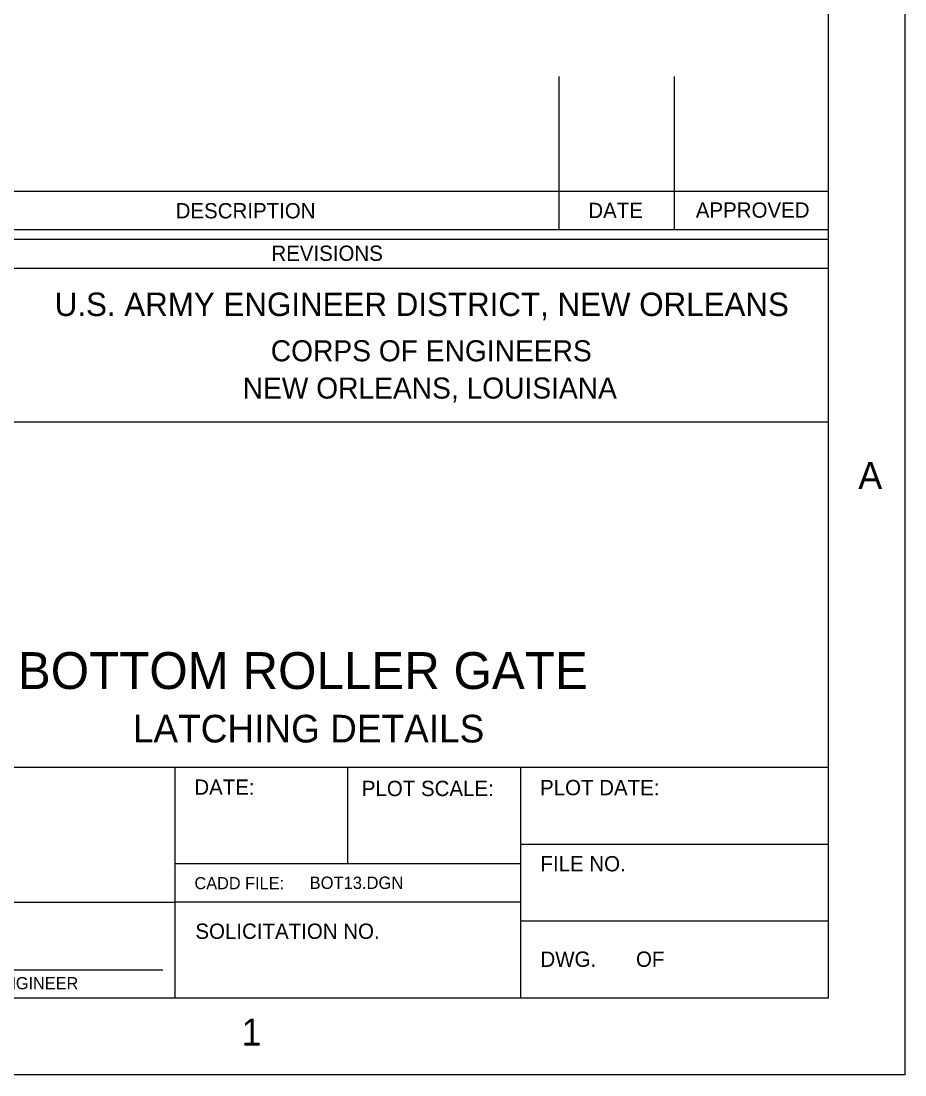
# Model space of a CAD drawing. Extents: x 0 to 320, y -4 to 473.
# Drawn here: x 308.95 to 320.45, y 417.42 to 431.14 of the extents above; entities that cross this region are included whole.
import ezdxf

# ---------------------------------------------------------------- set-up
doc = ezdxf.new("R2010")
doc.units = 0
doc.layers.add('Level 1', color=7, linetype='Continuous')
doc.layers.add('Level 2', color=7, linetype='Continuous')

msp = doc.modelspace()

# ---------------------------------------------------------------- linework, layer by layer
at = {"layer": 'Level 1'}
for p, q in [((315.949, 428.416), (315.949, 430.416)), ((317.449, 428.416), (317.449, 430.416)), ((319.449, 428.916), (306.449, 428.916)), ((319.449, 428.416), (306.449, 428.416)), ((319.449, 428.291), (306.449, 428.291)), ((319.449, 427.916), (306.449, 427.916)), ((319.449, 425.916), (306.449, 425.916)), ((319.449, 421.416), (306.449, 421.416)), ((310.949, 418.416), (310.949, 421.416)), ((313.199, 420.166), (313.199, 421.416)), ((315.449, 418.416), (315.449, 421.416)), ((319.449, 420.416), (315.449, 420.416)), ((315.449, 420.166), (310.949, 420.166)), ((306.449, 419.666), (310.949, 419.666)), ((315.449, 419.666), (310.949, 419.666)), ((319.449, 419.416), (315.449, 419.416)), ((306.583, 418.783), (310.789, 418.783))]:
    msp.add_line(p, q, dxfattribs=at)
for points in [[(240.449, 473.416), (320.449, 473.416), (320.449, 417.416), (240.449, 417.416)], [(243.449, 472.416), (319.449, 472.416), (319.449, 418.416), (243.449, 418.416)]]:
    msp.add_lwpolyline(points, close=True, dxfattribs=at)

# ---------------------------------------------------------------- texts
for s, height, p in [('DESCRIPTION', 0.19925, (310.957, 428.567)), ('DATE', 0.1992, (316.328, 428.571)), ('APPROVED', 0.1992, (317.727, 428.576)), ('REVISIONS', 0.1992, (312.203, 428.014)), ('U.S. ARMY ENGINEER DISTRICT, NEW ORLEANS', 0.30475, (309.383, 427.296)), ('CORPS OF ENGINEERS', 0.27428, (312.195, 426.706)), ('NEW ORLEANS, LOUISIANA', 0.27428, (311.829, 426.221)), ('A', 0.351, (319.841, 425.043)), ('DATE:', 0.1992, (311.2, 421.063)), ('PLOT SCALE:', 0.19925, (313.38, 421.046)), ('PLOT DATE:', 0.1992, (315.7, 421.057)), ('FILE NO.', 0.1992, (315.705, 420.066)), ('CADD FILE:', 0.1585, (311.202, 419.833)), ('SOLICITATION NO.', 0.19925, (311.214, 419.187)), ('DWG.       OF', 0.19925, (315.705, 418.823)), ('DESIGN ENGINEER', 0.1585, (307.711, 418.531)), ('1', 0.351, (311.814, 417.798))]:
    msp.add_text(s, height=height, dxfattribs=at).set_placement(p)
at = {"layer": 'Level 2'}
for s, height, p in [('BOTTOM ROLLER GATE', 0.48, (308.903, 422.44)), ('LATCHING DETAILS', 0.36, (310.4, 421.744)), ('BOT13.DGN', 0.1608, (312.701, 419.837))]:
    msp.add_text(s, height=height, dxfattribs=at).set_placement(p)

doc.saveas('drawing.dxf')
